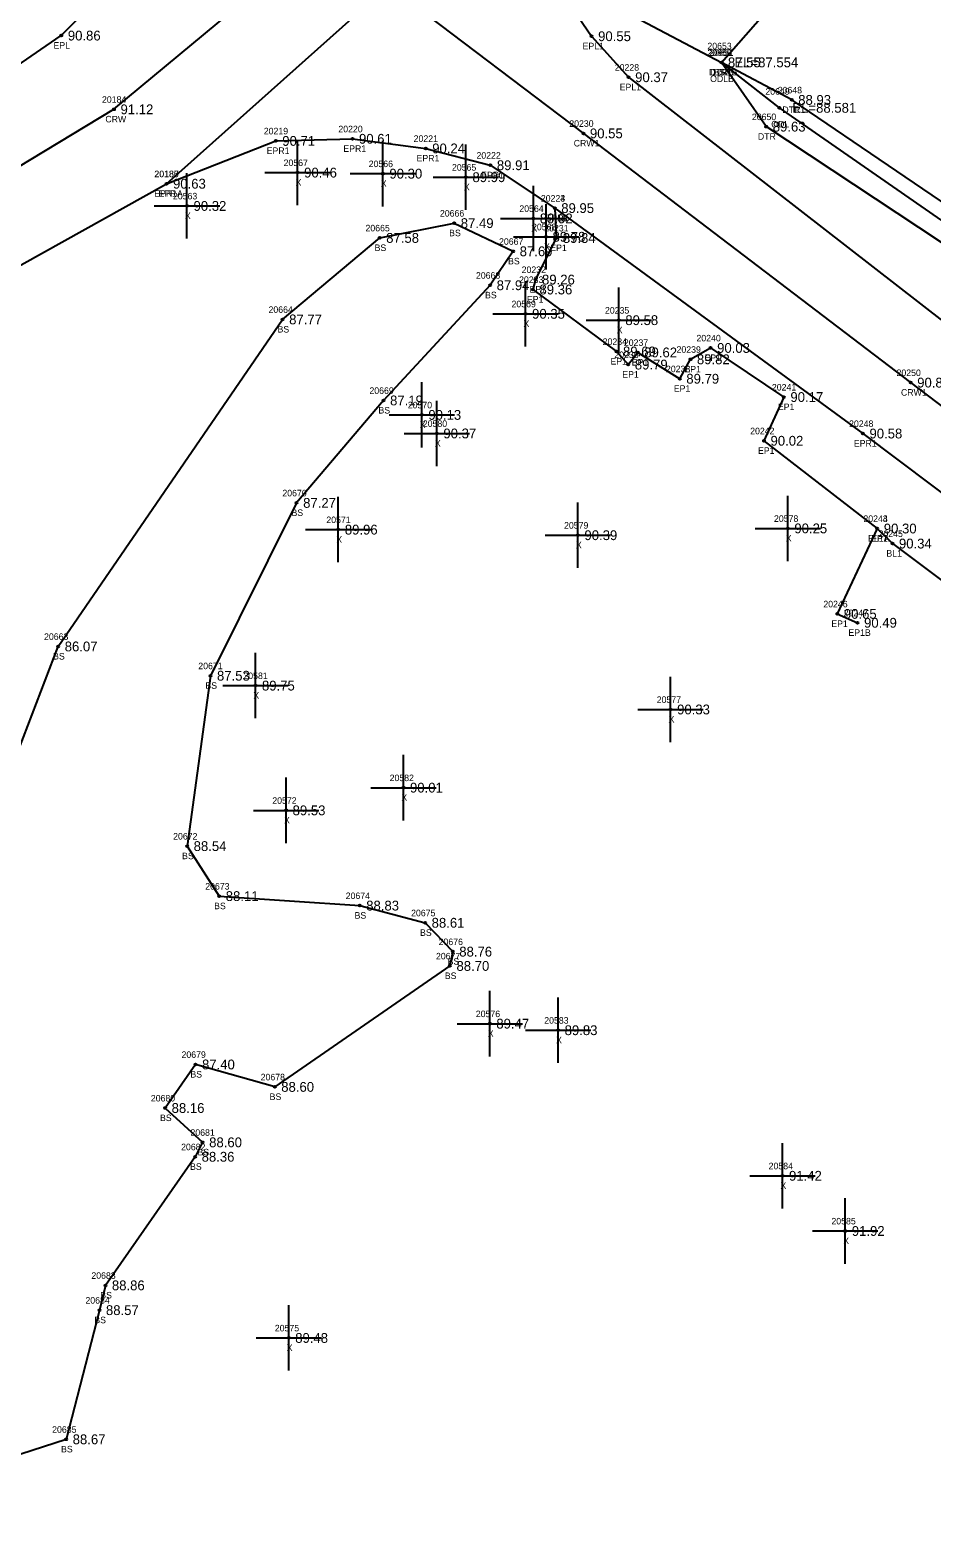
# Model space of a CAD drawing. Extents: x 2530197 to 2532051, y 935230 to 936631.
# Drawn here: x 2531709.5 to 2531847.5, y 936097.4 to 936328 of the extents above; entities that cross this region are included whole.
import ezdxf

# ---------------------------------------------------------------- set-up
doc = ezdxf.new("R2010")
doc.units = 0
for name, color, linetype in [('RD_DTM_BkLn1', 7, 'Continuous'), ('RD_DTM_BkLn2', 7, 'Continuous'), ('RD_DTM_BkLn_txCode', 7, 'Continuous'), ('RD_EX_H2O', 7, 'Continuous'), ('RD_EX_H2O_txCode', 7, 'Continuous'), ('RD_EX_Misc', 7, 'Continuous'), ('RD_EX_Misc_txCode', 7, 'Continuous'), ('RD_EX_Road', 7, 'Continuous'), ('RD_EX_Road_txCode', 7, 'Continuous'), ('RD_EX_TX_H2O_ELEV', 7, 'Continuous'), ('RD_EX_TX_Misc_ELEV', 7, 'Continuous'), ('RD_EX_TX_Road_ELEV', 7, 'Continuous'), ('RD_HC_Survey_ELEV', 7, 'Continuous'), ('RD_HC_Survey_txCode', 7, 'Continuous'), ('RD_SMD_Locator', 7, 'Continuous')]:
    doc.layers.add(name, color=color, linetype=linetype)

msp = doc.modelspace()

# ---------------------------------------------------------------- linework, layer by layer
at = {"layer": 'RD_DTM_BkLn1'}
for points in [[(2531175.16, 935992.09), (2531214.08, 936014.93), (2531297.2, 936064.16), (2531382.2, 936114.3), (2531466.12, 936163.77), (2531548.89, 936212.96), (2531632.55, 936261.89), (2531678, 936289.19), (2531722.34, 936315.93), (2531754.26, 936342.49), (2531759.78, 936349.83), (2531772.77, 936373.29), (2531778.96, 936389.71), (2531793.78, 936438.29), (2531813.65, 936511.36), (2531832.39, 936582.88)], [(2531766.68, 936333.11), (2531794.16, 936312.25), (2531844.23, 936274.13), (2531924.38, 936213.25), (2532005.14, 936152.12)], [(2531839.12, 936251.81), (2531841.44, 936249.51), (2531884.63, 936217.15), (2531903.05, 936202.75), (2531912.55, 936196.67)]]:
    msp.add_lwpolyline(points, dxfattribs=at)
at = {"layer": 'RD_DTM_BkLn2'}
for points in [[(2531917.54, 936550.96), (2531882.37, 936485.34), (2531845.03, 936416.88), (2531807.92, 936350.36), (2531800.08, 936331.1), (2531815.28, 936323.11), (2531842.04, 936353.56), (2531870.4, 936350.41), (2531903.53, 936402.83), (2531942.77, 936461.82), (2531965.7, 936452.8), (2531970.35, 936457.79), (2531954.01, 936477.47), (2531964.77, 936498.69)], [(2531701.14, 936200.83), (2531713.8, 936233.77), (2531748.14, 936283.79), (2531762.99, 936296.26), (2531774.4, 936298.52), (2531783.41, 936294.21), (2531779.89, 936289.02), (2531763.58, 936271.4), (2531750.28, 936255.73), (2531737.1, 936229.29), (2531733.53, 936203.23), (2531738.44, 936195.58), (2531759.93, 936194.13), (2531769.94, 936191.5), (2531774.17, 936187.09), (2531773.74, 936184.9), (2531746.93, 936166.4), (2531734.81, 936169.83), (2531730.16, 936163.17), (2531735.9, 936157.92), (2531734.75, 936155.71), (2531721.02, 936136.04), (2531720.11, 936132.25), (2531715.02, 936112.49), (2531699.5, 936107.49)]]:
    msp.add_lwpolyline(points, dxfattribs=at)
at = {"layer": 'RD_EX_H2O'}
for points in [[(2531884.72, 936272.64), (2531880.26, 936274.65), (2531857.03, 936293.37), (2531824.14, 936316.16), (2531815.27, 936323.11)], [(2531888.89, 936272.02), (2531887.88, 936268.95), (2531883.72, 936268.22), (2531855.58, 936291.19), (2531822.13, 936313.28), (2531815.27, 936323.11)], [(2531888.89, 936272.02), (2531858.16, 936295.56), (2531826.03, 936317.37), (2531815.27, 936323.11)]]:
    msp.add_lwpolyline(points, dxfattribs=at)
at = {"layer": 'RD_EX_Misc'}
for p, q in [((2531750.43, 936301.25), (2531750.43, 936311.25)), ((2531763.48, 936301.09), (2531763.48, 936311.09)), ((2531776.19, 936300.55), (2531776.19, 936310.55)), ((2531733.51, 936296.15), (2531733.51, 936306.15)), ((2531745.43, 936306.25), (2531755.43, 936306.25)), ((2531758.48, 936306.09), (2531768.48, 936306.09)), ((2531771.19, 936305.55), (2531781.19, 936305.55)), ((2531786.5, 936294.24), (2531786.5, 936304.24)), ((2531728.51, 936301.15), (2531738.51, 936301.15)), ((2531788.44, 936291.43), (2531788.44, 936301.43)), ((2531781.5, 936299.24), (2531791.5, 936299.24)), ((2531783.44, 936296.43), (2531793.44, 936296.43)), ((2531785.31, 936279.65), (2531785.31, 936289.65)), ((2531799.58, 936278.68), (2531799.58, 936288.68)), ((2531780.31, 936284.65), (2531790.31, 936284.65)), ((2531794.58, 936283.68), (2531804.58, 936283.68)), ((2531769.44, 936264.19), (2531769.44, 936274.19)), ((2531771.74, 936261.35), (2531771.74, 936271.35)), ((2531764.44, 936269.19), (2531774.44, 936269.19)), ((2531766.74, 936266.35), (2531776.74, 936266.35)), ((2531756.66, 936246.64), (2531756.66, 936256.64)), ((2531793.32, 936245.79), (2531793.32, 936255.79)), ((2531825.44, 936246.83), (2531825.44, 936256.83)), ((2531751.66, 936251.64), (2531761.66, 936251.64)), ((2531788.32, 936250.79), (2531798.32, 936250.79)), ((2531820.44, 936251.83), (2531830.44, 936251.83)), ((2531743.98, 936222.78), (2531743.98, 936232.78)), ((2531738.98, 936227.78), (2531748.98, 936227.78)), ((2531807.5, 936219.13), (2531807.5, 936229.13)), ((2531802.5, 936224.13), (2531812.5, 936224.13)), ((2531766.63, 936207.17), (2531766.63, 936217.17)), ((2531748.67, 936203.7), (2531748.67, 936213.7)), ((2531761.63, 936212.17), (2531771.63, 936212.17)), ((2531743.67, 936208.7), (2531753.67, 936208.7)), ((2531779.84, 936171.07), (2531779.84, 936181.07)), ((2531790.29, 936170.07), (2531790.29, 936180.07)), ((2531774.84, 936176.07), (2531784.84, 936176.07)), ((2531785.29, 936175.07), (2531795.29, 936175.07)), ((2531824.62, 936147.8), (2531824.62, 936157.8)), ((2531819.62, 936152.8), (2531829.62, 936152.8)), ((2531834.23, 936139.36), (2531834.23, 936149.36)), ((2531829.23, 936144.36), (2531839.23, 936144.36)), ((2531749.07, 936123), (2531749.07, 936133)), ((2531744.07, 936128), (2531754.07, 936128))]:
    msp.add_line(p, q, dxfattribs=at)
at = {"layer": 'RD_EX_Road'}
for points in [[(2531169.65, 936000.77), (2531208.79, 936024.95), (2531292.04, 936074.02), (2531376.24, 936123.7), (2531460.37, 936174.49), (2531542.92, 936223.44), (2531626.67, 936270.85), (2531672.4, 936298.39), (2531714.28, 936327.21), (2531747.19, 936360.45), (2531761.42, 936377.32), (2531773.11, 936411.11), (2531782.2, 936441.65), (2531803.17, 936514.76), (2531820.28, 936585.8)], [(2531180.82, 935982), (2531220.82, 936004.21), (2531303.54, 936053.39), (2531388.75, 936103.71), (2531472.27, 936152.98), (2531554.79, 936201.9), (2531638.11, 936250.92), (2531683.19, 936278.28), (2531730.37, 936304.55), (2531771.5, 936341.26), (2531788.67, 936375.53), (2531805.57, 936434.84), (2531825.53, 936508.74), (2531844.13, 936579.65)], [(2531788.67, 936375.53), (2531784.05, 936361.55), (2531786.68, 936344.28), (2531790.66, 936334.1), (2531795.41, 936327.11), (2531801.08, 936320.84), (2531849.6, 936283.17), (2531876.01, 936264.22), (2531894.71, 936249.13), (2531930.69, 936221.59), (2532010.91, 936160.51)], [(2531730.37, 936304.55), (2531747.09, 936311.1), (2531758.83, 936311.42), (2531770.03, 936309.95), (2531779.92, 936307.38), (2531789.77, 936300.82), (2531836.93, 936266.34), (2531918.06, 936205.29), (2531926.11, 936199.32), (2531961.6, 936172.59), (2531979.77, 936158.9), (2531999.31, 936144.02)], [(2531789.77, 936300.82), (2531790.01, 936296.25), (2531786.83, 936289.89), (2531786.44, 936288.37), (2531799.22, 936278.89), (2531801.03, 936276.89), (2531802.47, 936278.74), (2531808.91, 936274.72), (2531810.53, 936277.69), (2531813.62, 936279.43), (2531824.83, 936271.92), (2531821.79, 936265.23), (2531839.12, 936251.81), (2531833.01, 936238.75), (2531836.1, 936237.39)]]:
    msp.add_lwpolyline(points, dxfattribs=at)
at = {"layer": 'RD_SMD_Locator'}
for centre in [(2531714.28, 936327.21), (2531795.41, 936327.11), (2531815.27, 936323.11), (2531815.27, 936323.11), (2531815.27, 936323.11), (2531815.28, 936323.11), (2531801.08, 936320.84), (2531826.03, 936317.37), (2531722.34, 936315.93), (2531824.14, 936316.16), (2531794.16, 936312.25), (2531822.13, 936313.28), (2531747.09, 936311.1), (2531758.83, 936311.42), (2531770.03, 936309.95), (2531750.43, 936306.25), (2531763.48, 936306.09), (2531776.19, 936305.55), (2531779.92, 936307.38), (2531730.37, 936304.55), (2531730.37, 936304.55), (2531733.51, 936301.15), (2531789.77, 936300.82), (2531789.77, 936300.82), (2531774.4, 936298.52), (2531786.5, 936299.24), (2531762.99, 936296.26), (2531788.44, 936296.43), (2531790.01, 936296.25), (2531783.41, 936294.21), (2531786.83, 936289.89), (2531779.89, 936289.02), (2531786.44, 936288.37), (2531785.31, 936284.65), (2531748.14, 936283.79), (2531799.58, 936283.68), (2531799.22, 936278.89), (2531802.47, 936278.74), (2531810.53, 936277.69), (2531813.62, 936279.43), (2531801.03, 936276.89), (2531808.91, 936274.72), (2531844.23, 936274.13), (2531763.58, 936271.4), (2531824.83, 936271.92), (2531769.44, 936269.19), (2531771.74, 936266.35), (2531836.93, 936266.34), (2531821.79, 936265.23), (2531750.28, 936255.73), (2531756.66, 936251.64), (2531793.32, 936250.79), (2531825.44, 936251.83), (2531839.12, 936251.81), (2531839.12, 936251.81), (2531841.44, 936249.51), (2531833.01, 936238.75), (2531836.1, 936237.39), (2531713.8, 936233.77), (2531737.1, 936229.29), (2531743.98, 936227.78), (2531807.5, 936224.13), (2531766.63, 936212.17), (2531748.67, 936208.7), (2531733.53, 936203.23), (2531738.44, 936195.58), (2531759.93, 936194.13), (2531769.94, 936191.5), (2531774.17, 936187.09), (2531773.74, 936184.9), (2531779.84, 936176.07), (2531790.29, 936175.07), (2531734.81, 936169.83), (2531746.93, 936166.4), (2531730.16, 936163.17), (2531735.9, 936157.92), (2531734.75, 936155.71), (2531824.62, 936152.8), (2531834.23, 936144.36), (2531721.02, 936136.04), (2531720.11, 936132.25), (2531749.07, 936128), (2531715.02, 936112.49)]:
    msp.add_circle(centre, 0.15, dxfattribs=at)

# ---------------------------------------------------------------- texts
at = {"layer": 'RD_DTM_BkLn_txCode'}
for s, p in [('20989', (2531813.16, 936324.11)), ('BS2', (2531814.05, 936321.11)), ('20666', (2531772.21, 936299.52)), ('20665', (2531760.82, 936297.26)), ('BS', (2531773.62, 936296.52)), ('20667', (2531781.25, 936295.21)), ('BS', (2531762.21, 936294.26)), ('BS', (2531782.63, 936292.21)), ('20668', (2531777.72, 936290.02)), ('BS', (2531779.11, 936287.02)), ('20664', (2531745.98, 936284.79)), ('BS', (2531747.36, 936281.79)), ('20669', (2531761.42, 936272.4)), ('BS', (2531762.8, 936269.4)), ('20670', (2531748.1, 936256.73)), ('BS', (2531749.5, 936253.73)), ('20244', (2531837, 936252.81)), ('BL1A', (2531837.71, 936249.81)), ('20245', (2531839.32, 936250.51)), ('BL1', (2531840.52, 936247.51)), ('20663', (2531711.64, 936234.77)), ('BS', (2531713.02, 936231.77)), ('20671', (2531735.24, 936230.29)), ('BS', (2531736.32, 936227.29)), ('20672', (2531731.39, 936204.23)), ('BS', (2531732.76, 936201.23)), ('20673', (2531736.3, 936196.58)), ('20674', (2531757.79, 936195.13)), ('BS', (2531737.66, 936193.58)), ('BS', (2531759.15, 936192.13)), ('20675', (2531767.8, 936192.5)), ('BS', (2531769.16, 936189.5)), ('20676', (2531772.01, 936188.09)), ('20677', (2531771.6, 936185.9)), ('BS', (2531773.39, 936185.09)), ('BS', (2531772.96, 936182.9)), ('20679', (2531732.67, 936170.83)), ('BS', (2531734.03, 936167.83)), ('20678', (2531744.78, 936167.4)), ('20680', (2531727.98, 936164.17)), ('BS', (2531746.15, 936164.4)), ('BS', (2531729.38, 936161.17)), ('20681', (2531734.04, 936158.92)), ('20682', (2531732.61, 936156.71)), ('BS', (2531735.12, 936155.92)), ('BS', (2531733.97, 936153.71)), ('20683', (2531718.88, 936137.04)), ('BS', (2531720.24, 936134.04)), ('20684', (2531717.97, 936133.25)), ('BS', (2531719.33, 936130.25)), ('20685', (2531712.88, 936113.49)), ('BS', (2531714.24, 936110.49))]:
    msp.add_text(s, height=1, dxfattribs=at).set_placement(p)
at = {"layer": 'RD_EX_H2O_txCode'}
for s, p in [('20653', (2531813.13, 936325.11)), ('20652', (2531813.13, 936324.11)), ('20651', (2531813.41, 936324.11)), ('DTR1B', (2531813.37, 936321.11)), ('DTRB', (2531813.53, 936321.11)), ('ODLB', (2531813.55, 936320.11)), ('20648', (2531823.89, 936318.37)), ('20649', (2531822, 936318.16)), ('20650', (2531819.94, 936314.28)), ('DTR1', (2531824.6, 936315.37)), ('ODL', (2531822.9, 936313.16)), ('DTR', (2531820.86, 936311.28))]:
    msp.add_text(s, height=1, dxfattribs=at).set_placement(p)
at = {"layer": 'RD_EX_Misc_txCode'}
for s, p in [('20567', (2531748.29, 936307.25)), ('20566', (2531761.31, 936307.09)), ('20565', (2531774.05, 936306.55)), ('20563', (2531731.36, 936302.15)), ('X', (2531750.12, 936304.25)), ('X', (2531763.16, 936304.09)), ('X', (2531775.87, 936303.55)), ('20564', (2531784.36, 936300.24)), ('X', (2531733.19, 936299.15)), ('X', (2531786.19, 936297.24)), ('20568', (2531786.3, 936297.43)), ('X', (2531788.12, 936294.43)), ('20569', (2531783.16, 936285.65)), ('20235', (2531797.46, 936284.68)), ('X', (2531784.99, 936282.65)), ('X', (2531799.26, 936281.68)), ('20570', (2531767.29, 936270.19)), ('X', (2531769.13, 936267.19)), ('20580', (2531769.59, 936267.35)), ('X', (2531771.43, 936264.35)), ('20571', (2531754.83, 936252.64)), ('20579', (2531791.2, 936251.79)), ('20578', (2531823.32, 936252.83)), ('X', (2531756.35, 936249.64)), ('X', (2531825.12, 936249.83)), ('X', (2531793.01, 936248.79)), ('20581', (2531742.14, 936228.78)), ('X', (2531743.66, 936225.78)), ('20577', (2531805.38, 936225.13)), ('X', (2531807.19, 936222.13)), ('20582', (2531764.51, 936213.17)), ('X', (2531766.31, 936210.17)), ('20572', (2531746.56, 936209.7)), ('X', (2531748.36, 936206.7)), ('20576', (2531777.7, 936177.07)), ('20583', (2531788.17, 936176.07)), ('X', (2531779.53, 936174.07)), ('X', (2531789.98, 936173.07)), ('20584', (2531822.5, 936153.8)), ('X', (2531824.31, 936150.8)), ('20585', (2531832.11, 936145.36)), ('X', (2531833.92, 936142.36)), ('20575', (2531746.95, 936129)), ('X', (2531748.76, 936126))]:
    msp.add_text(s, height=1, dxfattribs=at).set_placement(p)
at = {"layer": 'RD_EX_Road_txCode'}
for s, p in [('EPL', (2531713.08, 936325.21)), ('EPL1', (2531794.04, 936325.11)), ('20228', (2531798.96, 936321.84)), ('EPL1', (2531799.71, 936318.84)), ('20219', (2531745.26, 936312.1)), ('20220', (2531756.67, 936312.42)), ('EPR1', (2531745.7, 936309.1)), ('EPR1', (2531757.43, 936309.42)), ('20221', (2531768.19, 936310.95)), ('EPR1', (2531768.63, 936307.95)), ('20222', (2531777.8, 936308.38)), ('20186', (2531728.51, 936305.55)), ('20187', (2531728.54, 936305.55)), ('EPR1', (2531778.52, 936305.38)), ('EPR1A', (2531728.49, 936302.55)), ('EPR', (2531729.14, 936302.55)), ('20223', (2531787.65, 936301.82)), ('20224', (2531787.65, 936301.82)), ('EP1A', (2531788.36, 936298.82)), ('EPR1', (2531788.38, 936298.82)), ('20231', (2531788.17, 936297.25)), ('EP1', (2531789.09, 936294.25)), ('20232', (2531784.71, 936290.89)), ('20233', (2531784.32, 936289.37)), ('EP1', (2531785.52, 936286.37)), ('EP1', (2531785.91, 936287.89)), ('20234', (2531797.11, 936279.89)), ('20237', (2531800.35, 936279.74)), ('20240', (2531811.46, 936280.43)), ('EP1', (2531798.3, 936276.89)), ('20236', (2531798.89, 936277.89)), ('20239', (2531808.41, 936278.69)), ('EP1', (2531812.69, 936277.43)), ('EP1', (2531800.11, 936274.89)), ('EP1', (2531801.55, 936276.74)), ('20238', (2531806.79, 936275.72)), ('EP1', (2531809.61, 936275.69)), ('EP1', (2531807.99, 936272.72)), ('20241', (2531823, 936272.92)), ('EP1', (2531823.91, 936269.92)), ('20242', (2531819.68, 936266.23)), ('20248', (2531834.81, 936267.34)), ('EP1', (2531820.87, 936263.23)), ('EPR1', (2531835.54, 936264.34)), ('20243', (2531837, 936252.81)), ('EP1', (2531838.2, 936249.81)), ('20246', (2531830.87, 936239.75)), ('20247', (2531833.98, 936238.39)), ('EP1', (2531832.09, 936236.75)), ('EP1B', (2531834.71, 936235.39))]:
    msp.add_text(s, height=1, dxfattribs=at).set_placement(p)
at = {"layer": 'RD_EX_TX_H2O_ELEV'}
for s, p in [('87.55', (2531816.27, 936322.36)), ('87.55', (2531816.27, 936322.36)), ('EL=87.554', (2531817.27, 936322.36)), ('88.93', (2531827.03, 936316.62)), ('EL=88.581', (2531826.14, 936315.41)), ('89.63', (2531823.13, 936312.53))]:
    msp.add_text(s, height=1.5, dxfattribs=at).set_placement(p)
at = {"layer": 'RD_EX_TX_Misc_ELEV'}
for s, p in [('87.55', (2531816.28, 936322.36)), ('90.46', (2531751.43, 936305.5)), ('90.30', (2531764.48, 936305.34)), ('89.99', (2531777.19, 936304.8)), ('90.32', (2531734.51, 936300.4)), ('87.49', (2531775.4, 936297.77)), ('89.92', (2531787.5, 936298.49)), ('87.58', (2531763.99, 936295.51)), ('89.78', (2531789.44, 936295.68)), ('87.69', (2531784.41, 936293.46)), ('87.94', (2531780.89, 936288.27)), ('90.35', (2531786.31, 936283.9)), ('87.77', (2531749.14, 936283.04)), ('89.58', (2531800.58, 936282.93)), ('87.19', (2531764.58, 936270.65)), ('90.13', (2531770.44, 936268.44)), ('90.37', (2531772.74, 936265.6)), ('87.27', (2531751.28, 936254.98)), ('89.96', (2531757.66, 936250.89)), ('90.25', (2531826.44, 936251.08)), ('90.30', (2531840.12, 936251.06)), ('90.39', (2531794.32, 936250.04)), ('90.34', (2531842.44, 936248.76)), ('86.07', (2531714.8, 936233.02)), ('87.53', (2531738.1, 936228.54)), ('89.75', (2531744.98, 936227.03)), ('90.33', (2531808.5, 936223.38)), ('90.01', (2531767.63, 936211.42)), ('89.53', (2531749.67, 936207.95)), ('88.54', (2531734.53, 936202.48)), ('88.11', (2531739.44, 936194.83)), ('88.83', (2531760.93, 936193.38)), ('88.61', (2531770.94, 936190.75)), ('88.76', (2531775.17, 936186.34)), ('88.70', (2531774.74, 936184.15)), ('89.47', (2531780.84, 936175.32)), ('89.83', (2531791.29, 936174.32)), ('87.40', (2531735.81, 936169.08)), ('88.60', (2531747.93, 936165.65)), ('88.16', (2531731.16, 936162.42)), ('88.60', (2531736.9, 936157.17)), ('88.36', (2531735.75, 936154.96)), ('91.42', (2531825.62, 936152.05)), ('91.92', (2531835.23, 936143.61)), ('88.86', (2531722.02, 936135.29)), ('88.57', (2531721.11, 936131.5)), ('89.48', (2531750.07, 936127.25)), ('88.67', (2531716.02, 936111.74))]:
    msp.add_text(s, height=1.5, dxfattribs=at).set_placement(p)
at = {"layer": 'RD_EX_TX_Road_ELEV'}
for s, p in [('90.86', (2531715.28, 936326.46)), ('90.55', (2531796.41, 936326.36)), ('90.37', (2531802.08, 936320.09)), ('90.71', (2531748.09, 936310.35)), ('90.61', (2531759.83, 936310.67)), ('90.24', (2531771.03, 936309.2)), ('89.91', (2531780.92, 936306.63)), ('90.63', (2531731.37, 936303.8)), ('90.63', (2531731.37, 936303.8)), ('89.95', (2531790.77, 936300.07)), ('89.95', (2531790.77, 936300.07)), ('89.84', (2531791.01, 936295.5)), ('89.26', (2531787.83, 936289.14)), ('89.36', (2531787.44, 936287.62)), ('90.03', (2531814.62, 936278.68)), ('89.69', (2531800.22, 936278.14)), ('89.62', (2531803.47, 936277.99)), ('89.82', (2531811.53, 936276.94)), ('89.79', (2531802.03, 936276.14)), ('89.79', (2531809.91, 936273.97)), ('90.17', (2531825.83, 936271.17)), ('90.58', (2531837.93, 936265.59)), ('90.02', (2531822.79, 936264.48)), ('90.30', (2531840.12, 936251.06)), ('90.65', (2531834.01, 936238)), ('90.49', (2531837.1, 936236.64))]:
    msp.add_text(s, height=1.5, dxfattribs=at).set_placement(p)
at = {"layer": 'RD_HC_Survey_ELEV'}
for s, p in [('91.12', (2531723.34, 936315.18)), ('90.55', (2531795.16, 936311.5)), ('90.89', (2531845.23, 936273.38))]:
    msp.add_text(s, height=1.5, dxfattribs=at).set_placement(p)
at = {"layer": 'RD_HC_Survey_txCode'}
for s, p in [('20184', (2531720.5, 936316.93)), ('CRW', (2531721.02, 936313.93)), ('20230', (2531792, 936313.25)), ('CRW1', (2531792.68, 936310.25)), ('20250', (2531842.07, 936275.13)), ('CRW1', (2531842.75, 936272.13))]:
    msp.add_text(s, height=1, dxfattribs=at).set_placement(p)

doc.saveas('drawing.dxf')
